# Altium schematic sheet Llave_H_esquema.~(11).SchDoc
size A4
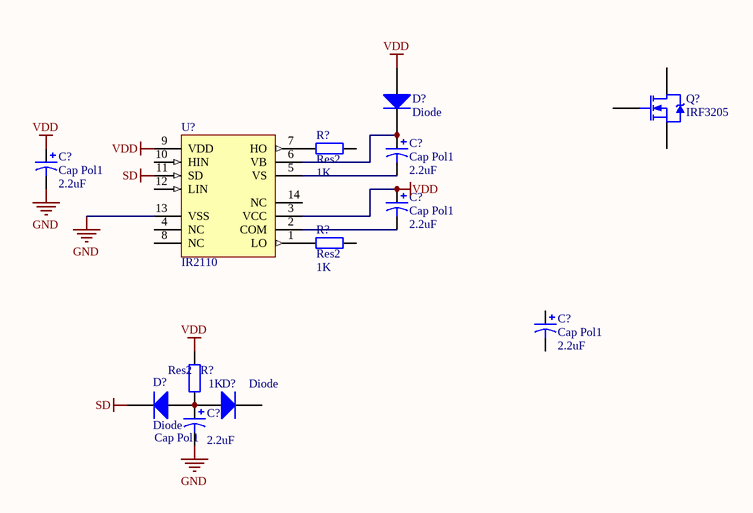
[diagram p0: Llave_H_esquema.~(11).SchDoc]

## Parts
(Parts that share a designator on the sheet are numbered #1, #2 ... from top to bottom, then left to right.)
C?#1  Cap Pol1  value 2.2uF  [RB7.6-15]
C?#2  Cap Pol1  value 2.2uF  [RB7.6-15]
C?#3  Cap Pol1  value 2.2uF  [RB7.6-15]
C?#4  Cap Pol1  value 2.2uF  [RB7.6-15]
C?#5  Cap Pol1  value 2.2uF  [RB7.6-15]
D?#1  Diode  [SMC]
D?#2  Diode  [SMC]
D?#3  Diode  [SMC]
Q?  IRF3205  [TO-220AB]
R?#1  Res2  value 1K  [AXIAL-0.4]
R?#2  Res2  value 1K  [AXIAL-0.4]
R?#3  Res2  value 1K  [AXIAL-0.4]
U?  IR2110  [PDIP14]

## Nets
GND: C?#2.2 C?#5.2 U?.13(VSS)
SD: D?#3.2(K) U?.11(SD)
VDD: C?#2.1 C?#3.1 D?#1.1(A) R?#3.2 U?.3(VCC) U?.9(VDD)
NetC?#1_1: C?#1.1 D?#1.2(K) U?.6(VB)
NetC?#1_2: C?#1.2 U?.5(VS)
NetC?#3_2: C?#3.2 U?.2(COM)
NetC?#5_1: C?#5.1 D?#2.1(A) D?#3.1(A) R?#3.1
NetR?#1_1: R?#1.1 U?.7(HO)
NetR?#2_1: R?#2.1 U?.1(LO)

Not connected (* = marked no-connect by the designer): C?#4 1 2; D?#2 2(K); Q? 1(G) 2(D) 3(S); R?#1 2; R?#2 2; U? 4(NC) 8(NC) 10(HIN) 12(LIN) 14(NC)

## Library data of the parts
C?#1-C?#5 = Cap Pol1: Polarized Capacitor (Radial)
D?#1-D?#3 = Diode: Default Diode
Q? = IRF3205: HEXFET Power MOSFET; Note: Pin 2 is electrically connected to pin 4.
R?#1-R?#3 = Res2: Resistor
U? = IR2110: High and Low Side Driver; Note: Pins 4, 8 and 14 are not connected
